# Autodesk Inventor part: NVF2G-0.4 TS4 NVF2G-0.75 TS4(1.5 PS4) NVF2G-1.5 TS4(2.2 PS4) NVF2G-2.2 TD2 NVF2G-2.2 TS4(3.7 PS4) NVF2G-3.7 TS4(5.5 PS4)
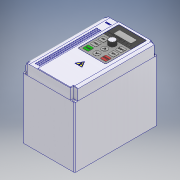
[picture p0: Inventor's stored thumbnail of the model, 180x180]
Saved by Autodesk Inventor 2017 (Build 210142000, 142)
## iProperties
Part Number: NVF2G-0.4 TS4 NVF2G-0.75 TS4(1.5 PS4) NVF2G-1.5 TS4(2.2 PS4) NVF2G-2.2 TD2 NVF2G-2.2 TS4(3.7 PS4) NVF2G-3.7 TS4(5.5 PS4)
Material: Типовые
Document SubType Name: Modeling
Designer: RSagdiev
Density: 1 g/cm^3
Appearance: По умолчанию
Author: RSagdiev
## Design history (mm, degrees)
sketch "Эскиз1"
  geometry: L1 (0, 0)-(44.679, 0) reference; L2 (0, 0)-(0, 56.035) reference; L3 (0, 0)-(187, 0); L4 (187, 0)-(187, 137.6); L5 (187, 137.6)-(0, 137.6); L6 (0, 137.6)-(0, 0)
  constraints: 12 end point, 3 horizontal, 2 parallel, 2 vertical, 1 perpendicular
  dimensions: "d0" = 187 distance of L5.end L4.end; "d1" = 137.6 distance of L4.end L3.end
extrude "Выдавливание1" new body sketch "Эскиз1" stored distance "d2" = 118; taper "d3" = 0 deg
sketch "Эскиз2"
  geometry: L1 (0, 0)-(0, 187) reference; L2 (118, 0)-(118, 187) reference; L3 (0, 187)-(10, 187); L4 (118, 187)-(118, 180); L5 (118, 0)-(108, 0); L6 (0, 0)-(0, 7); L7 (0, 187)-(118, 187) reference; L8 (0, 187)-(10, 187); L9 (10, 187)-(10, 180); L10 (10, 180)-(0, 180); L11 (0, 180)-(0, 187); L12 (118, 187)-(108, 187); L13 (108, 187)-(108, 180); L14 (108, 180)-(118, 180); L15 (118, 180)-(118, 187); L16 (0, 0)-(118, 0) reference; L17 (0, 0)-(10, 0); L18 (10, 0)-(10, 7); L19 (10, 7)-(0, 7); L20 (0, 7)-(0, 0); L21 (118, 0)-(108, 0); L22 (108, 0)-(108, 7); L23 (108, 7)-(118, 7); L24 (118, 7)-(118, 0); L25 (10, 187)-(108, 187); L26 (0, 180)-(0, 187); L27 (108, 187)-(118, 187); L28 (118, 180)-(118, 7); L29 (108, 0)-(10, 0); L30 (118, 7)-(118, 0); L31 (10, 0)-(0, 0); L32 (0, 7)-(0, 180); 1 further point
  constraints: 56 end point, 26 parallel, 13 perpendicular, 7 horizontal
  dimensions: "d4" = 10 distance of L9.end L10.end; "d5" = 7 distance of L3.end L9.end; "d6" = 10 distance of L4.end L13.end; "d7" = 7 distance of L13.end L12.end; "d8" = 10 distance of L6.end L18.end; "d9" = 7 distance of L18.end L17.end; "d10" = 10 distance of L22.end L23.end; "d11" = 7 distance of L5.end L22.end
extrude "Выдавливание2" new body sketch "Эскиз2" distance "d12" = 24; taper "d13" = 0 deg
chamfer "Фаска1" distance "d14" = 4; stored, may be unused: second distance "d15" = 2, angle "d16" = 45 deg
sketch "Эскиз3"
  geometry: L1 (10, 183)-(34.5, 183); L2 (10, 183)-(10, 180); L3 (10, 180)-(0, 180); L4 (0, 180)-(0, 7); L5 (0, 7)-(10, 7); L6 (10, 7)-(10, 0); L7 (10, 0)-(34.5, 0); L8 (108, 0)-(108, 7); L9 (108, 7)-(118, 7); L10 (118, 7)-(118, 180); L11 (118, 180)-(108, 180); L12 (108, 180)-(108, 183); L13 (10, 183)-(108, 183) reference; L14 (34.5, 183)-(34.5, 0); L15 (0, 0)-(118, 0) reference; L16 (34.5, 183)-(108, 183); L17 (34.5, 0)-(108, 0); 1 further point
  constraints: 10 end point, 2 perpendicular, 2 point on line
  dimensions: "d19" = 83.5 distance between parallel lines of L14 L10
extrude "Выдавливание3" new body sketch "Эскиз3" distance "d17" = 2; taper "d18" = 0 deg
sketch "Эскиз4"
  geometry: L1 (101, 178)-(42, 178); L2 (40, 176)-(40, 87); L3 (42, 85)-(101, 85); L4 (103, 87)-(103, 176); L5 (118, 7)-(118, 180) reference; L6 (10, 183)-(108, 183) reference; A1 r 2 centre (42, 176) between (42, 178) and (40, 176); A2 r 2 centre (101, 176) between (103, 176) and (101, 178); A3 r 2 centre (101, 87) between (101, 85) and (103, 87); A4 r 2 centre (42, 87) between (40, 87) and (42, 85); 4 further points
  constraints: 8 end point, 8 point on circle, 8 tangent, 6 point on line, 4 centre point, 3 equal radius, 2 parallel, 1 horizontal, 1 perpendicular
  dimensions: "d20" = 63 distance of point (103, 85) point (40, 85); "d21" = 93 distance of point (40, 85) point (40, 178); "d22" = 15 distance between parallel lines of L4 L5; "d23" = 5 distance between parallel lines of L6 L1; "d24" = 2 radius of A1
extrude "Выдавливание4" cut sketch "Эскиз4" distance "d25" = 0.6; taper "d26" = 0 deg
sketch "Эскиз5"
  geometry: L1 (0, 187)-(118, 187) reference; L2 (0, 0)-(0, 187) reference; L3 (118, 187)-(118, 0) reference; L4 (0, 0)-(118, 0) reference; C1 r 2.5 at (5.5, 183.5); C2 r 2.5 at (112.5, 183.5); C3 r 2.5 at (5.5, 3.5); C4 r 2.5 at (112.5, 3.5); 1 further point
  constraints: 4 centre point
  dimensions: "d27" = 5 diameter of C1; "d28" = 3.5 distance from line of C1.centre L1; "d29" = 5.5 distance from line of C1.centre L2; "d30" = 5 diameter of C2; "d31" = 3.5 distance from line of C2.centre L1; "d32" = 5.5 distance from line of C2.centre L3; "d33" = 5 diameter of C3; "d34" = 3.5 distance from line of L4 C3.centre; "d35" = 5.5 distance from line of C3.centre L2; "d36" = 5 diameter of C4; "d37" = 5.5 distance from line of C4.centre L3; "d38" = 3.5 distance from line of C4.centre L4
extrude "Выдавливание5" cut sketch "Эскиз5" stored distance "d39" = 0.6; taper "d40" = 0 deg
sketch "Эскиз6"
  geometry: L1 (40, 87)-(40, 143); L2 (101, 85)-(42, 85); L3 (103, 176)-(103, 143); L4 (42, 178)-(101, 178); L5 (40, 87)-(40, 176) reference; L6 (40, 143)-(103, 143); L7 (103, 176)-(103, 87) reference; L8 (40, 143)-(40, 176); L9 (103, 143)-(103, 87); L10 (53.5, 154)-(89.5, 154); L11 (91.5, 156)-(91.5, 166); L12 (89.5, 168)-(53.5, 168); L13 (51.5, 166)-(51.5, 156); L14 (51.5, 154)-(91.5, 168); L15 (91.5, 154)-(51.5, 168); L16 (71.5, 131.5)-(71.5, 96.857); L17 (63.25, 131.5)-(63.25, 96.857); L18 (79.75, 96.857)-(79.75, 131.5); L19 (57, 138)-(46, 138); L20 (45, 137)-(45, 126); L21 (46, 125)-(57, 125); L22 (58, 126)-(58, 137); L23 (58, 138)-(45, 125); L24 (45, 138)-(58, 125); L25 (91.5, 156)-(91.5, 157.5); L26 (51.5, 131.5)-(75.409, 131.5); L27 (26.654, 114.179)-(72.729, 114.179); L28 (26.654, 96.857)-(71.963, 96.857); L29 (98, 126)-(98, 137); L30 (86, 125)-(97, 125); L31 (98, 138)-(85, 125); L32 (85, 138)-(98, 125); L33 (85, 137)-(85, 126); L34 (97, 138)-(86, 138); L35 (98, 108.679)-(98, 119.679); L36 (86, 107.679)-(97, 107.679); L37 (98, 120.679)-(85, 107.679); L38 (85, 120.679)-(98, 107.679); L39 (85, 119.679)-(85, 108.679); L40 (97, 120.679)-(86, 120.679); L41 (98, 91.357)-(98, 102.357); L42 (86, 90.357)-(97, 90.357); L43 (98, 103.357)-(85, 90.357); L44 (85, 103.357)-(98, 90.357); L45 (85, 102.357)-(85, 91.357); L46 (97, 103.357)-(86, 103.357); L47 (58, 91.357)-(58, 102.357); L48 (46, 90.357)-(57, 90.357); L49 (58, 103.357)-(45, 90.357); L50 (45, 103.357)-(58, 90.357); L51 (45, 102.357)-(45, 91.357); L52 (57, 103.357)-(46, 103.357); L53 (58, 108.679)-(58, 119.679); L54 (46, 107.679)-(57, 107.679); L55 (58, 120.679)-(45, 107.679); L56 (45, 120.679)-(58, 107.679); L57 (45, 119.679)-(45, 108.679); L58 (57, 120.679)-(46, 120.679); L59 (101, 85)-(42, 85) reference; L60 (103, 176)-(103, 87) reference; L61 (51.5, 131.5)-(51.5, 91.5); C1 r 6.5 at (71.5, 131.5); C2 r 6.5 at (71.5, 96.857); C3 r 6.5 at (71.5, 114.179); A1 r 2 centre (53.5, 166) between (53.5, 168) and (51.5, 166); A2 r 2 centre (89.5, 166) between (91.5, 166) and (89.5, 168); A3 r 2 centre (89.5, 156) between (89.5, 154) and (91.5, 156); A4 r 2 centre (53.5, 156) between (51.5, 156) and (53.5, 154); A5 r 8.25 centre (71.5, 131.5) between (79.75, 131.5) and (63.25, 131.5); A6 r 8.25 centre (71.5, 96.857) between (63.25, 96.857) and (79.75, 96.857); A7 r 1 centre (57, 137) between (58, 137) and (57, 138); A8 r 1 centre (57, 126) between (57, 125) and (58, 126); A9 r 1 centre (46, 126) between (45, 126) and (46, 125); A10 r 1 centre (46, 137) between (46, 138) and (45, 137); A11 r 1 centre (97, 126) between (97, 125) and (98, 126); A12 r 1 centre (97, 137) between (98, 137) and (97, 138); A13 r 1 centre (86, 137) between (86, 138) and (85, 137); A14 r 1 centre (86, 126) between (85, 126) and (86, 125); A15 r 1 centre (97, 108.679) between (97, 107.679) and (98, 108.679); A16 r 1 centre (97, 119.679) between (98, 119.679) and (97, 120.679); A17 r 1 centre (86, 119.679) between (86, 120.679) and (85, 119.679); A18 r 1 centre (86, 108.679) between (85, 108.679) and (86, 107.679); A19 r 1 centre (97, 91.357) between (97, 90.357) and (98, 91.357); A20 r 1 centre (97, 102.357) between (98, 102.357) and (97, 103.357); A21 r 1 centre (86, 102.357) between (86, 103.357) and (85, 102.357); A22 r 1 centre (86, 91.357) between (85, 91.357) and (86, 90.357); A23 r 1 centre (57, 91.357) between (57, 90.357) and (58, 91.357); A24 r 1 centre (57, 102.357) between (58, 102.357) and (57, 103.357); A25 r 1 centre (46, 102.357) between (46, 103.357) and (45, 102.357); A26 r 1 centre (46, 91.357) between (45, 91.357) and (46, 90.357); A27 r 1 centre (57, 108.679) between (57, 107.679) and (58, 108.679); A28 r 1 centre (57, 119.679) between (58, 119.679) and (57, 120.679); A29 r 1 centre (46, 119.679) between (46, 120.679) and (45, 119.679); A30 r 1 centre (46, 108.679) between (45, 108.679) and (46, 107.679); A31 r 2 centre (42, 176) between (42, 178) and (40, 176) reference; A32 r 2 centre (101, 176) between (103, 176) and (101, 178) reference; A33 r 2 centre (101, 87) between (101, 85) and (103, 87) reference; A34 r 2 centre (42, 87) between (40, 87) and (42, 85) reference; 17 further points
  constraints: 112 end point, 70 point on line, 60 point on circle, 60 tangent, 33 centre point, 22 midpoint, 21 equal radius, 15 parallel, 11 horizontal, 7 perpendicular, 3 coincident, 3 vertical
  dimensions: "d43" = 35 distance between parallel lines of L4 L6; "d44" = 40 distance of L15.end L14.end; "d45" = 14 distance of L14.end L15.start; "d46" = 10 distance between parallel lines of L4 L12; "d47" = 2 radius of A1; "d48" = 11.5 distance between parallel lines of L8 L13; "d49" = 16.5 diameter of A6; "d50" = 31.5 distance between parallel lines of L1 L16; "d51" = 11.5 distance from line of L6 L16.start; "d52" = 11.85714 distance from line of L2 L16.end; "d53" = 13 diameter of C1; "d54" = 13 diameter of C2; "d55" = 13 diameter of C3; "d56" = 13 distance of L24.end L23.end; "d57" = 13 distance of L23.end L24.start; "d58" = 1 radius of A7 (derived); "d59" = 11.5 distance from line of L6 L26.start; "d60" = 11.5 distance from line of L5 L26.start; "d61" = 13 distance of L32.end L31.end; "d62" = 13 distance of L31.end L32.start; "d63" = 1 radius of A12 (derived); "d64" = 13 distance of L38.end L37.end; "d65" = 13 distance of L37.end L38.start; "d66" = 1 radius of A16 (derived); "d67" = 13 distance of L44.end L43.end; "d68" = 13 distance of L43.end L44.start; "d69" = 1 radius of A20 (derived); "d70" = 13 distance of L50.end L49.end; "d71" = 13 distance of L49.end L50.start; "d72" = 1 radius of A24 (derived); "d73" = 13 distance of L56.end L55.end; "d74" = 13 distance of L55.end L56.start; "d75" = 1 radius of A28 (derived)
extrude "Выдавливание6" new body sketch "Эскиз6" distance "d76" = 0.3; taper "d77" = 0 deg
extrude "Выдавливание7" new body sketch "Эскиз6" distance "d78" = 0.6; taper "d79" = 0 deg
sketch "Эскиз7"
  geometry: L1 (40, 143)-(103, 143) reference; L2 (103, 176)-(103, 87) reference; L3 (40, 143)-(103, 143); L4 (103, 143)-(103, 143.1); L5 (103, 143.1)-(40, 143.1); L6 (40, 143.1)-(40, 143); 1 further point
  constraints: 8 end point, 2 parallel, 1 horizontal, 1 perpendicular, 1 point on line
  dimensions: "d80" = 0.1 distance of L4.end L3.end
extrude "Выдавливание8" cut sketch "Эскиз7" distance "d81" = 0.3; taper "d82" = 0 deg
sketch "Эскиз8" dims "d91" = 10
  geometry: L1 (40, 143.1)-(103, 143.1) reference; L2 (40, 87)-(40, 176) reference; C1 r 1 at (48, 148.1); C2 r 1 at (55.75, 148.1); C3 r 1 at (63.5, 148.1); C4 r 1 at (71.25, 148.1); C5 r 1 at (79, 148.1); C6 r 1 at (86.75, 148.1); C7 r 1 at (94.5, 148.1); 1 further point
  constraints: 7 centre point, 1 horizontal, 12 other
  dimensions: "d83" = 2 diameter of C1; "d84" = 5 distance from line of C1.centre L1; "d85" = 8 distance from line of C1.centre L2; "d88" = 7.75 distance of C1.centre C2.centre
extrude "Выдавливание9" join sketch "Эскиз8" distance "d93" = 0.3; taper "d94" = 0 deg
sketch "Эскиз9"
  geometry: C1 r 6.5 at (0, 0) reference; C2 r 7.5 at (0, 0); 1 further point
  constraints: 1 centre point, 1 coincident
  dimensions: "d95" = 15 diameter of C2
extrude "Выдавливание10" join sketch "Эскиз9" distance "d96" = 9.4; taper "d97" = -3 deg
sketch "Эскиз10"
  geometry: L1 (0, 7.331)-(0.619, 6.259); L2 (0.619, 6.259)-(-0.619, 6.259); L3 (-0.619, 6.259)-(0, 7.331); 2 further points
  constraints: 6 end point, 7 other
sketch "Эскиз11"
  geometry: L1 (0, 7.917)-(0.884, 6.386); L2 (0.884, 6.386)-(-0.884, 6.386); L3 (-0.884, 6.386)-(0, 7.917); 2 further points
  constraints: 6 end point, 7 other
feature "Лофт1" sketch "Эскиз10", "Эскиз11" dims "d98" = 0, "d99" = 90 deg, "d100" = 0, "d101" = 90 deg
sketch "Эскиз12"
  geometry: L1 (48.043, 133.259)-(54.263, 133.259); L2 (54.263, 133.259)-(54.263, 129.759); L3 (54.263, 129.759)-(48.043, 129.759); L4 (48.043, 129.759)-(48.043, 133.259); L5 (47.093, 116.16)-(55.948, 116.16); L6 (55.948, 116.16)-(55.948, 112.53); L7 (55.948, 112.53)-(47.093, 112.53); L8 (47.093, 112.53)-(47.093, 116.16); L9 (46.736, 98.824)-(56.093, 98.824); L10 (56.093, 98.824)-(56.093, 95.25); L11 (56.093, 95.25)-(46.736, 95.25); L12 (46.736, 95.25)-(46.736, 98.824); L13 (85.565, 98.824)-(97.118, 98.824); L14 (97.118, 98.824)-(97.118, 95.176); L15 (97.118, 95.176)-(85.565, 95.176); L16 (85.565, 95.176)-(85.565, 98.824); L17 (87.346, 116.041)-(95.541, 116.041); L18 (95.541, 116.041)-(95.541, 112.417); L19 (95.541, 112.417)-(87.346, 112.417); L20 (87.346, 112.417)-(87.346, 116.041); L21 (85.447, 133.378)-(98.496, 133.378); L22 (98.496, 133.378)-(98.496, 129.753); L23 (98.496, 129.753)-(85.447, 129.753); L24 (85.447, 129.753)-(85.447, 133.378); 1 further point
  constraints: 12 other
feature "Рельеф1" dims "d105" = 0.1, "d106" = 0
feature "Рельеф2" dims "d107" = 0.1, "d108" = 0
feature "Рельеф3" dims "d109" = 0.1, "d110" = 0
feature "Рельеф4" dims "d111" = 0.1, "d112" = 0
feature "Рельеф5" dims "d113" = 0.1, "d114" = 0
feature "Рельеф6" dims "d115" = 0.1, "d116" = 0
sketch "Эскиз13"
  geometry: L1 (-3.144, -2.347)-(-0.04, 3.728); L2 (-0.04, 3.728)-(3.298, -2.347); L3 (3.298, -2.347)-(2.096, -2.347); L4 (2.096, -2.347)-(-0.04, 1.541); L5 (-0.04, 1.541)-(-2.027, -2.347); L6 (-2.027, -2.347)-(-3.144, -2.347); L7 (-9.387, -8.657)-(8.031, -8.657); L8 (-3.144, -14.967)-(-0.04, -21.041); L9 (-0.04, -21.041)-(3.298, -14.967); L10 (3.298, -14.967)-(2.096, -14.967); L11 (2.096, -14.967)-(-0.04, -18.855); L12 (-0.04, -18.855)-(-2.027, -14.967); L13 (-2.027, -14.967)-(-3.144, -14.967); 1 further point
  constraints: 26 end point, 6 symmetric about line, 2 horizontal, 2 parallel, 2 point on line, 1 collinear
feature "Рельеф7" dims "d117" = 0.1, "d118" = 0
feature "Рельеф8" dims "d119" = 0.1, "d120" = 0
sketch "Эскиз14"
  geometry: L1 (74.211, 66.244)-(82.508, 51.874); L2 (82.508, 51.874)-(65.915, 51.874); L3 (65.915, 51.874)-(74.211, 66.244); L4 (81.081, 52.698)-(74.211, 64.596); L5 (74.211, 64.596)-(67.342, 52.698); L6 (67.342, 52.698)-(81.081, 52.698); L7 (73.384, 60.929)-(72.444, 57.119); L8 (72.444, 57.119)-(74.865, 57.289); L9 (74.865, 57.289)-(73.824, 54.973); L10 (73.824, 54.973)-(72.874, 55.4); L11 (72.874, 55.4)-(73.031, 53.169); L12 (73.031, 53.169)-(75.501, 54.218); L13 (75.501, 54.218)-(74.82, 54.525); L14 (74.82, 54.525)-(76.749, 58.161); L15 (76.749, 58.161)-(73.595, 57.978); L16 (73.595, 57.978)-(75.161, 60.929); L17 (75.161, 60.929)-(73.384, 60.929); 2 further points
  constraints: 34 end point, 2 perpendicular, 2 point on line, 1 parallel, 9 other
extrude "Выдавливание11" cut sketch "Эскиз14" distance "d121" = 0.1; taper "d122" = 0 deg
extrude "Выдавливание12" join sketch "Эскиз14" distance "d123" = 0.05; taper "d124" = 0 deg
sketch "Эскиз15"
  geometry: L1 (41.547, 152.524)-(66.241, 152.524); L2 (66.241, 152.524)-(66.241, 149.637); L3 (66.241, 149.637)-(41.547, 149.637); L4 (41.547, 149.637)-(41.547, 152.524); L5 (67.282, 152.078)-(98.223, 152.078); L6 (98.223, 152.078)-(98.223, 147.987); L7 (98.223, 147.987)-(67.282, 147.987); L8 (67.282, 147.987)-(67.282, 152.078); 1 further point
  constraints: 4 other
feature "Рельеф9" sketch "Эскиз15" dims "d125" = 0.1, "d126" = 0
sketch "Эскиз16" dims "d133" = 10, "d140" = 10
  geometry: L1 (-46.348, 158.18)-(-46.348, 136.213); L2 (-47.848, 158.18)-(-47.848, 136.213); L3 (-44.848, 136.213)-(-44.848, 158.18); L4 (0, 169)-(24, 169); L5 (-40.348, 158.18)-(-40.348, 136.213); L6 (-41.848, 158.18)-(-41.848, 136.213); L7 (-38.848, 136.213)-(-38.848, 158.18); L8 (-34.348, 158.18)-(-34.348, 136.213); L9 (-35.848, 158.18)-(-35.848, 136.213); L10 (-32.848, 136.213)-(-32.848, 158.18); L11 (-28.348, 158.18)-(-28.348, 136.213); L12 (-29.848, 158.18)-(-29.848, 136.213); L13 (-26.848, 136.213)-(-26.848, 158.18); L14 (-22.348, 158.18)-(-22.348, 136.213); L15 (-23.848, 158.18)-(-23.848, 136.213); L16 (-20.848, 136.213)-(-20.848, 158.18); L17 (-47.848, 128.18)-(-47.848, 106.213); L18 (-46.348, 128.18)-(-46.348, 106.213); L19 (-44.848, 106.213)-(-44.848, 128.18); L20 (-41.848, 128.18)-(-41.848, 106.213); L21 (-38.848, 106.213)-(-38.848, 128.18); L22 (-35.848, 128.18)-(-35.848, 106.213); L23 (-34.348, 128.18)-(-34.348, 106.213); L24 (-32.848, 106.213)-(-32.848, 128.18); L25 (-29.848, 128.18)-(-29.848, 106.213); L26 (-28.348, 128.18)-(-28.348, 106.213); L27 (-26.848, 106.213)-(-26.848, 128.18); L28 (-23.848, 128.18)-(-23.848, 106.213); L29 (-22.348, 128.18)-(-22.348, 106.213); L30 (-20.848, 106.213)-(-20.848, 128.18); L31 (-40.348, 128.18)-(-40.348, 106.213); L32 (-47.848, 98.18)-(-47.848, 76.213); L33 (-46.348, 98.18)-(-46.348, 76.213); L34 (-44.848, 76.213)-(-44.848, 98.18); L35 (-41.848, 98.18)-(-41.848, 76.213); L36 (-38.848, 76.213)-(-38.848, 98.18); L37 (-35.848, 98.18)-(-35.848, 76.213); L38 (-34.348, 98.18)-(-34.348, 76.213); L39 (-32.848, 76.213)-(-32.848, 98.18); L40 (-29.848, 98.18)-(-29.848, 76.213); L41 (-28.348, 98.18)-(-28.348, 76.213); L42 (-26.848, 76.213)-(-26.848, 98.18); L43 (-23.848, 98.18)-(-23.848, 76.213); L44 (-22.348, 98.18)-(-22.348, 76.213); L45 (-20.848, 76.213)-(-20.848, 98.18); L46 (-40.348, 98.18)-(-40.348, 76.213); L47 (-47.848, 68.18)-(-47.848, 46.213); L48 (-46.348, 68.18)-(-46.348, 46.213); L49 (-44.848, 46.213)-(-44.848, 68.18); L50 (-41.848, 68.18)-(-41.848, 46.213); L51 (-38.848, 46.213)-(-38.848, 68.18); L52 (-35.848, 68.18)-(-35.848, 46.213); L53 (-34.348, 68.18)-(-34.348, 46.213); L54 (-32.848, 46.213)-(-32.848, 68.18); L55 (-29.848, 68.18)-(-29.848, 46.213); L56 (-28.348, 68.18)-(-28.348, 46.213); L57 (-26.848, 46.213)-(-26.848, 68.18); L58 (-23.848, 68.18)-(-23.848, 46.213); L59 (-22.348, 68.18)-(-22.348, 46.213); L60 (-20.848, 46.213)-(-20.848, 68.18); L61 (-40.348, 68.18)-(-40.348, 46.213); A1 r 1.5 centre (-46.348, 158.18) between (-44.848, 158.18) and (-47.848, 158.18); A2 r 1.5 centre (-46.348, 136.213) between (-47.848, 136.213) and (-44.848, 136.213); A3 r 1.5 centre (-40.348, 158.18) between (-38.848, 158.18) and (-41.848, 158.18); A4 r 1.5 centre (-40.348, 136.213) between (-41.848, 136.213) and (-38.848, 136.213); A5 r 1.5 centre (-34.348, 158.18) between (-32.848, 158.18) and (-35.848, 158.18); A6 r 1.5 centre (-34.348, 136.213) between (-35.848, 136.213) and (-32.848, 136.213); A7 r 1.5 centre (-28.348, 158.18) between (-26.848, 158.18) and (-29.848, 158.18); A8 r 1.5 centre (-28.348, 136.213) between (-29.848, 136.213) and (-26.848, 136.213); A9 r 1.5 centre (-22.348, 158.18) between (-20.848, 158.18) and (-23.848, 158.18); A10 r 1.5 centre (-22.348, 136.213) between (-23.848, 136.213) and (-20.848, 136.213); A11 r 1.5 centre (-46.348, 106.213) between (-47.848, 106.213) and (-44.848, 106.213); A12 r 1.5 centre (-40.348, 128.18) between (-38.848, 128.18) and (-41.848, 128.18); A13 r 1.5 centre (-46.348, 128.18) between (-44.848, 128.18) and (-47.848, 128.18); A14 r 1.5 centre (-34.348, 128.18) between (-32.848, 128.18) and (-35.848, 128.18); A15 r 1.5 centre (-22.348, 128.18) between (-20.848, 128.18) and (-23.848, 128.18); A16 r 1.5 centre (-28.348, 128.18) between (-26.848, 128.18) and (-29.848, 128.18); A17 r 1.5 centre (-40.348, 106.213) between (-41.848, 106.213) and (-38.848, 106.213); A18 r 1.5 centre (-34.348, 106.213) between (-35.848, 106.213) and (-32.848, 106.213); A19 r 1.5 centre (-28.348, 106.213) between (-29.848, 106.213) and (-26.848, 106.213); A20 r 1.5 centre (-22.348, 106.213) between (-23.848, 106.213) and (-20.848, 106.213); A21 r 1.5 centre (-46.348, 76.213) between (-47.848, 76.213) and (-44.848, 76.213); A22 r 1.5 centre (-40.348, 98.18) between (-38.848, 98.18) and (-41.848, 98.18); A23 r 1.5 centre (-46.348, 98.18) between (-44.848, 98.18) and (-47.848, 98.18); A24 r 1.5 centre (-34.348, 98.18) between (-32.848, 98.18) and (-35.848, 98.18); A25 r 1.5 centre (-22.348, 98.18) between (-20.848, 98.18) and (-23.848, 98.18); A26 r 1.5 centre (-28.348, 98.18) between (-26.848, 98.18) and (-29.848, 98.18); A27 r 1.5 centre (-40.348, 76.213) between (-41.848, 76.213) and (-38.848, 76.213); A28 r 1.5 centre (-34.348, 76.213) between (-35.848, 76.213) and (-32.848, 76.213); A29 r 1.5 centre (-28.348, 76.213) between (-29.848, 76.213) and (-26.848, 76.213); A30 r 1.5 centre (-22.348, 76.213) between (-23.848, 76.213) and (-20.848, 76.213); A31 r 1.5 centre (-46.348, 46.213) between (-47.848, 46.213) and (-44.848, 46.213); A32 r 1.5 centre (-40.348, 68.18) between (-38.848, 68.18) and (-41.848, 68.18); A33 r 1.5 centre (-46.348, 68.18) between (-44.848, 68.18) and (-47.848, 68.18); A34 r 1.5 centre (-34.348, 68.18) between (-32.848, 68.18) and (-35.848, 68.18); A35 r 1.5 centre (-22.348, 68.18) between (-20.848, 68.18) and (-23.848, 68.18); A36 r 1.5 centre (-28.348, 68.18) between (-26.848, 68.18) and (-29.848, 68.18); A37 r 1.5 centre (-40.348, 46.213) between (-41.848, 46.213) and (-38.848, 46.213); A38 r 1.5 centre (-34.348, 46.213) between (-35.848, 46.213) and (-32.848, 46.213); A39 r 1.5 centre (-28.348, 46.213) between (-29.848, 46.213) and (-26.848, 46.213); A40 r 1.5 centre (-22.348, 46.213) between (-23.848, 46.213) and (-20.848, 46.213); 20 further points
  constraints: 162 end point, 80 point on circle, 40 centre point, 4 tangent, 2 vertical, 1 collinear, 1 horizontal, 1 midpoint, 1 parallel, 227 other
  dimensions: "d127" = 3 diameter of A2; "d130" = 6 distance of L2.start L6.start; "d137" = 30 distance of L6.end L20.end
extrude "Выдавливание13" cut sketch "Эскиз16" distance "d142" = 18.55; taper "d143" = 0 deg
sketch "Эскиз17"
  geometry: L1 (18.337, 171.226)-(25.336, 171.226); L2 (25.336, 171.226)-(25.336, 169.157); L3 (25.336, 169.157)-(18.337, 169.157); L4 (18.337, 169.157)-(18.337, 171.226); 1 further point
  constraints: 2 other
feature "Рельеф10" sketch "Эскиз17" dims "d144" = 0.1, "d145" = 0
fillet "Сопряжение3" dims "d146" = 15
sketch "Эскиз19" dims "d156" = 10
  geometry: L1 (20, 148.103)-(22, 148.103); L2 (22, 148.103)-(22, 8.103); L3 (22, 8.103)-(20, 8.103); L4 (20, 8.103)-(20, 148.103); L5 (15, 0)-(15, 183) reference; L6 (15, 0)-(108, 0) reference; L7 (24, 148.103)-(26, 148.103); L8 (26, 148.103)-(26, 8.103); L9 (26, 8.103)-(24, 8.103); L10 (24, 8.103)-(24, 148.103); L11 (28, 148.103)-(30, 148.103); L12 (30, 148.103)-(30, 8.103); L13 (30, 8.103)-(28, 8.103); L14 (28, 8.103)-(28, 148.103); 1 further point
  constraints: 24 end point, 2 horizontal, 2 parallel, 1 collinear, 1 perpendicular, 15 other
  dimensions: "d147" = 2 distance of L2.end L3.end; "d148" = 140 distance of L1.end L2.end; "d149" = 5 distance between parallel lines of L5 L4; "d150" = 8.10314 distance between parallel lines of L3 L6; "d153" = 4 distance of L1.start L7.start
extrude "Выдавливание14" cut sketch "Эскиз19" distance "d158" = 0.5; taper "d159" = 0 deg
fillet "Сопряжение4" dims "d160" = 2
node "Твердое тело1"
pattern_circular "Круговой массив1" dims angle "d103" = 360 deg
node "Твердое тело2"
node "Твердое тело3"
node "Твердое тело4"
node "Твердое тело5"
